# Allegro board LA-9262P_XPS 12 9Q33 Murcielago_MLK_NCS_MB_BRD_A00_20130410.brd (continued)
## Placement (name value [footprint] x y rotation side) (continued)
R537  -  [R_0402]  166.22 57.7 90 top
R540  -  [R_0402]  168.23 75.68 0 top
R541  -  [R_0805]  166.39 77.11 0 top
R545  -  [R_0402]  159.06 77.94 180 top
R555  -  [R_0402]  214.18 41.19 270 bottom
R556  -  [R_0402]  215.2 41.19 270 bottom
R560  -  [R_0402]  212.29 41.19 270 bottom
R565  -  [R_0402]  213.3 41.19 270 bottom
R604  -  [R_0402]  136.36 54.95 0 top
R607  -  [R_0402]  145.18 66.04 270 top
R608  -  [R_0402]  131.16 71.72 270 top
R741  -  [R0402_0OHM]  181.39 37.1 270 top
R742  -  [R0402_0OHM]  182.4 37.1 270 top
R811  -  [R_0603]  133.47 52.92 0 top
R819  -  [R0402_0OHM]  154.92 67.14 0 top
R854  -  [R_0402]  155.38 55.64 90 top
R855  -  [R_0402]  154.11 55.64 90 top
R884  -  [R_0402]  6.1 22.01 180 top
R886  -  [R_0402]  9.63 21.6 270 top
R888  -  [R_0402]  215.07 56.81 270 top
R889  -  [R_0402]  214.05 56.81 270 top
R890  -  [R_0402]  214.7 64.05 270 bottom
R891  -  [R_0402]  215.72 64.05 270 bottom
R892  -  [R_0402]  213.68 64.05 270 bottom
R893  -  [R_0402]  212.67 64.05 270 bottom
R910  -  [R_0402]  230.18 15.3 270 top
R911  -  [R_0402]  230.18 11.74 270 top
R912  -  [R_0402]  230.18 9.45 270 top
R913  -  [R_0402]  230.18 6.09 90 top
R916  -  [R_0402]  230.18 4.88 270 top
R920  -  [R_0402]  229.31 4.88 270 top
R921  -  [R0402_0OHM]  148.37 68.64 90 top
R922  -  [R_0402]  150.55 60.21 90 top
R924  -  [R_0402]  136.36 53.17 0 top
R925  -  [R0402_0OHM]  147.56 63.31 0 top
R926  -  [R0402_0OHM]  140.27 52.46 90 top
R927  -  [R_0402]  146.34 53.07 90 top
R928  -  [R_0402]  147.2 53.99 270 top
R929  -  [R_0402]  136.38 59.02 0 top
R930  -  [R_0402]  146.1 67.82 270 top
R931  -  [R0402_0OHM]  149.61 67.77 270 top
R934  -  [R0402_0OHM]  158.19 52.26 0 top
R939  -  [R_0402]  132.65 54.11 90 top
R941  -  [R_0402]  131.63 54.11 90 top
R942  -  [R_0402]  189.67 37.07 270 top
R943  -  [R_0402]  172.9 27.01 180 top
R944  -  [R_0402]  173.02 24.17 90 top
R945  -  [R_0402]  172.13 25.08 270 top
R953  -  [R_0402]  26.3 19.6 0 bottom
R955  -  [R_0402]  26.29 21.41 0 bottom
R957  -  [R_0402]  26.29 23.32 0 bottom
R973  -  [R_0402]  156.78 30.52 270 bottom
R974  -  [R0402_0OHM]  155.76 29.6 90 bottom
R975  -  [R_0402]  132.26 71.01 90 top
R977  -  [R_0402]  177.11 75.96 90 bottom
R978  -  [R_0402]  176.22 76.87 270 bottom
R980  -  [R_0402]  137.29 61.68 180 top
R982  -  [R0402_0OHM]  148.71 66.85 90 top
R983  -  [R0402_0OHM]  150.48 77.44 0 top
R984  -  [R0402_0OHM]  150.48 76.49 0 top
R985  -  [R_0402]  152.66 77.44 0 top
R986  -  [R_0402]  152.67 76.48 0 top
R989  -  [R_0402]  176.46 25.92 90 top
R990  -  [R_0402]  175.19 22.77 180 top
R1003  -  [R_0402]  152.39 66.26 0 top
R1004  -  [R_0402]  181.93 72.78 90 bottom
R1005  -  [R_0402]  180.92 72.78 90 bottom
R1006  -  [R0402_0OHM]  165.54 75.83 90 bottom
R1007  -  [R0402_0OHM]  164.52 75.83 90 bottom
R1008  -  [R0402_0OHM]  163.63 75.83 90 bottom
R1009  -  [R0402_0OHM]  162.62 75.83 90 bottom
R1010  -  [R0402_0OHM]  160.98 75.83 90 bottom
R1011  -  [R0402_0OHM]  159.96 75.83 90 bottom
R1026  -  [R_0402]  174.81 68.03 270 top
R1027  -  [R_0402]  133.29 21.62 180 bottom
R1032  -  [R_0402]  141.64 52.59 90 top
R1033  -  [R_0402]  159.15 74.05 270 bottom
R1034  -  [R_0402]  161.82 73.14 90 bottom
R1088  -  [R_0402]  153.18 55.54 90 top
R1090  -  [R_0402]  152.39 68.03 0 top
R1091  -  [R_0402]  145.13 73.36 180 top
R1092  -  [R_0402]  155.84 66.26 180 top
R1099  -  [R_0402]  154.93 62.45 0 top
R1100  -  [R_0402]  154.74 30.52 270 bottom
R1103  -  [R_0402]  6.1 21.12 180 top
R1115  -  [R_0402]  150.46 68.77 180 top
R1116  -  [R_0402]  150.57 67.63 0 top
R1117  -  [R_0402]  206 44.67 180 top
R1118  -  [R_0402]  206.86 44.67 0 top
R1125  -  [R0603_0OHM]  124.96 34.63 180 top
R1128  -  [R0603_0OHM]  178.11 34.76 270 top
R1131  -  [R0402_0OHM]  189.3 38.67 0 top
R1132  -  [R_0402]  23.66 53.47 180 top
R1133  -  [R0402_0OHM]  144.91 68.92 180 top
R1135  -  [R0402_0OHM]  159.58 67.96 90 top
R1136  -  [R_0402]  158.69 67.96 90 top
R1137  -  [R_0402]  196.91 41.31 180 top
R1139  -  [R_0402]  180.27 75.96 90 bottom
R1140  -  [R_0402]  130.41 31.71 0 top
R1141  -  [R_0402]  152.39 68.92 0 top
R1142  -  [R_0402]  157.79 29.6 90 bottom
R1143  -  [R_0402]  151.4 68.57 90 top
R1146  -  [R0402_0OHM]  132.38 22.59 0 bottom
R1152  -  [R0402_0OHM]  152.51 73.75 0 top
R1153  -  [R0402_0OHM]  152.51 74.64 0 top
R1154  -  [R_0402]  144 69.81 0 top
R1156  -  [R_0402]  129.52 58.64 0 top
R1158  -  [R0402_0OHM]  163.56 64.86 0 top
R1160  -  [R_0402]  125.29 60.36 90 top
R1161  -  [R_0402]  158.43 85.76 270 top
R1162  -  [R_0402]  174.81 69.89 270 top
R1163  -  [R_0402]  176.45 41.11 90 top
R1164  -  [R_0402]  202.03 40.08 270 top
R1165  -  [R_0402]  207.7 38.52 270 top
R1166  -  [R0402_0OHM]  205.42 38.52 270 top
R1167  -  [R_0402]  203.5 40.07 270 top
R1169  -  [R_0402]  111.63 72.48 270 bottom
R1175  -  [R_0402]  154.48 82.61 270 top
R1176  -  [R_0402]  145.99 73.36 0 top
R1179  -  [R_0402]  52.72 79.72 0 top
R1180  -  [R_0402]  22.75 52.58 0 top
R1182  -  [R_0402]  130.41 30.7 0 top
R1183  -  [R_0402]  127.18 60.49 270 top
R1185  -  [R_0402]  111.6 73.39 0 bottom
R1186  -  [R_0402]  131.69 43.98 270 top
R1187  -  [R_0402]  132.65 42.13 0 top
R1188  -  [R0402_0OHM]  194.84 53.48 270 top
R1190  -  [R_0402]  117.08 64.86 0 top
R1191  -  [R_0402]  117.08 66.64 0 top
R1197  -  [R_0402]  196.91 40.39 180 top
R1198  -  [R_0402]  35.67 45.81 0 top
R1199  -  [R0402_0OHM]  190.22 40.88 180 top
R1200  -  [R_0402]  190.65 43.69 90 top
R1202  -  [R_0402]  168.85 63.14 180 top
R1203  -  [R_0402]  173.68 67.32 90 top
R1204  -  [R0402_0OHM]  186.71 54.85 90 top
R1205  -  [R0402_0OHM]  140.76 76.96 180 top
R1206  -  [R_0402]  139.85 76.07 0 top
R1207  -  [R_0402]  165.41 66.48 180 top
R1208  -  [R0402_0OHM]  196.18 45.02 270 top
R1209  -  [R_0402]  197.09 45.02 270 top
R1210  -  [R_0402]  193.53 41.27 270 top
R1211  -  [R_0402]  58.13 84.21 90 top
R1212  -  [R_0402]  194.44 41.27 270 top
R1213  -  [R_0402]  206.31 38.52 270 top
R1214  -  [R_0402]  173.17 59.78 180 top
R1215  -  [R_0402]  173.17 58.85 180 top
R1216  -  [R0402_0OHM]  175.94 61.48 180 top
R1217  -  [R_0402]  216.14 46.08 180 top
R1218  -  [R_0402]  152.51 73.75 0 bottom
R1219  -  [R_0402]  152.51 74.64 0 bottom
R1220  -  [R_0402]  160.2 59.22 270 top
R1221  -  [R0402_0OHM]  158.43 58.56 90 top
R1222  -  [R0402_0OHM]  157.54 58.56 90 top
R1223  -  [R_0402]  155.76 59.73 270 top
R1224  -  [R_0402]  164.47 62.06 180 top
R1225  -  [R_0402]  164.47 62.95 180 top
R1226  -  [R0603_0OHM]  178.57 40.35 0 top
R1227  -  [R_0402]  165.08 58.57 270 top
R1228  -  [R_0402]  153.73 29.6 90 bottom
R1238  -  [R0402_0OHM]  135.41 76.26 0 top
R1239  -  [R_0402]  135.41 77.15 0 top
R1240  -  [R_1206]  94.15 74.51 180 top
R1241  -  [R_0402]  56.35 84.21 90 top
R1242  -  [R0603_0OHM]  160.71 31.03 270 bottom
R1247  -  [R0402_0OHM]  167.19 44.08 90 top
R1249  -  [R_0402]  127.18 61.48 90 top
R1250  -  [R_0402]  169.35 46.06 0 top
R1251  -  [R_0402]  154.88 58.81 90 top
R1252  -  [R0402_0OHM]  162.01 58.31 90 top
R1253  -  [R_0402]  162.87 59.22 270 top
R1255  -  [R_0402]  193.69 43.68 90 top
R1257  -  [R0402_0OHM]  136.52 27.27 0 top
R1258  -  [R0402_0OHM]  136.52 26.38 0 top
R1261  -  [R_0402]  118.66 39.13 0 top
R1262  -  [R_0402]  118.66 40.02 0 top
R1263  -  [R_0402]  125.48 52.49 270 top
R1264  -  [R_0402]  118.66 37.35 0 top
R1265  -  [R_0402]  124.47 52.49 270 top
R1266  -  [R_0402]  118.66 38.24 0 top
R1279  -  [R_0402]  181.16 75.96 90 bottom
R1281  -  [R_0402]  173.79 54.57 0 top
R1282  -  [R_0402]  173.04 51.09 270 top
R1283  -  [R_0402]  172.92 44.97 90 top
R1284  -  [R_0402]  175.08 45.89 270 top
R1285  -  [R_0402]  172.16 51.09 270 top
R1286  -  [R_0402]  171.27 51.09 270 top
R1287  -  [R_0402]  170.38 50.18 90 top
R1289  -  [R_0402]  163.21 54.19 180 top
R1290  -  [R_0402]  159.15 49.62 180 top
R1291  -  [R_0402]  160.4 54.19 0 top
R1292  -  [R_0402]  162.96 47.97 180 top
R1293  -  [R0402_0OHM]  157.28 49.57 270 top
R1294  -  [R0402_0OHM]  159.15 48.65 180 top
R1295  -  [R_0402]  159.15 50.51 180 top
R1296  -  [R_0402]  159.15 51.4 180 top
R1297  -  [R_0402]  147.49 69.56 270 top
R1299  -  [R_0402]  132.98 28.59 90 bottom
R1305  -  [R0603_0OHM]  132.77 22.95 270 top
R1306  -  [R_0603]  131.38 22.95 270 top
R1307  -  [R_0402]  150.93 71.64 90 top
R1308  -  [R_0402]  147.67 72.28 270 top
R1309  -  [R_0402]  22.75 44.96 0 top
R1310  -  [R_0402]  133.07 63.25 180 top
R1311  -  [R_0402]  21.86 47.08 180 bottom
R1312  -  [R_0402]  22.41 50.43 90 top
R1313  -  [R_0402]  187.33 42.6 270 top
R1314  -  [R0402_0OHM]  188.22 42.6 270 top
R1318  -  [R0603_0OHM]  125.05 30.82 180 top
R1319  -  [R0603_0OHM]  168.33 50.25 90 top
R1320  -  [R0603_0OHM]  121.28 60.03 180 top
R1322  -  [R0805_0OHM]  171.11 77.91 270 bottom
R1324  -  [R_0402]  35.16 54.53 0 bottom
R1325  -  [R_0402]  37.83 54.53 180 bottom
R1326  -  [R0603_0OHM]  121.3 56.73 180 top
R1327  -  [R_0402]  188.16 36.21 90 top
R1328  -  [R_0402]  187.27 36.21 90 top
R1338  -  [R_0402]  168.85 64.03 180 top
R1341  -  [R_0402]  94.7 48.33 90 top
R1342  -  [R_0402]  183.78 73.11 180 bottom
R1346  -  [R_0402]  114.71 50.89 0 top
R1347  -  [R_0402]  114.71 51.79 0 top
R1348  -  [R_0402]  113.02 54.97 90 top
R1349  -  [R_0402]  112.06 54.97 90 top
R1350  -  [R_0402]  114.71 52.69 0 top
R1351  -  [R_0402]  114.71 50 0 top
R1353  -  [R0402_0OHM]  144.22 72.45 0 top
R1354  -  [R_0402]  137.29 57.67 180 top
R1355  -  [R_1206]  110.08 60.93 90 top
R1360  -  [R_0402]  184.04 41.16 270 top
R1361  -  [R_0402]  183.34 36.21 90 top
R1362  -  [R_0402]  184.22 36.21 90 top
R1363  -  [R_0402]  185.12 36.21 90 top
R1364  -  [R_0402]  186.01 36.21 90 top
R1365  -  [R_0402]  186.38 41.95 270 top
R1366  -  [R_0402]  162.92 46.95 0 top
R1367  -  [R_0402]  161.09 59.22 270 top
R1368  -  [R_0402]  188.23 44.59 270 top
R1369  -  [R_0402]  189.49 44.6 270 top
R1370  -  [R_0402]  191.66 44.59 270 top
R1371  -  [R_0402]  192.68 44.59 270 top
R1372  -  [R0402_0OHM]  125.15 38.11 90 top
R1373  -  [R_0402]  131.76 41.24 180 top
R1374  -  [R_0402]  131.76 42.13 180 top
R1375  -  [R_0402]  125.25 50.48 270 top
R1376  -  [R_0402]  153.42 75.68 180 bottom
R1377  -  [R_0402]  138.41 30.95 270 top
R1378  -  [R_0402]  139.33 30.95 270 top
R1379  -  [R_0402]  118.52 78.63 0 top
R1380  -  [R_0402]  118.52 77.51 0 top
R1381  -  [R_0402]  117.52 73.88 180 top
R1382  -  [R0402_0OHM]  126.18 61.28 270 top
R1384  -  [R_0402]  169.48 75.2 270 bottom
R1385  -  [R_0402]  167.63 74.31 0 bottom
R1386  -  [R_0402]  131.57 57.57 90 top
R1387  -  [R_0402]  138.03 30.43 180 bottom
R1388  -  [R_0402]  173.44 39.07 270 top
R1389  -  [R_0402]  153.23 76.62 0 bottom
R1390  -  [R0402_0OHM]  119.13 64.45 0 bottom
R1391  -  [R_0402]  120.05 63.56 180 bottom
R1392  -  [R0603_0OHM]  158.45 75.22 0 top
R1393  -  [R0603_0OHM]  157.89 72.31 180 top
R1394  -  [R_0402]  153.42 75.55 180 top
R1395  -  [R_0402]  182.82 39.64 90 top
RA1  -  [R_0402]  124.33 50.46 270 top
RA5  -  [R_0402]  131.71 47.33 180 top
RA6  -  [R_0402]  131.71 48.22 180 top
RA7  -  [R_0402]  124.26 39.03 270 top
RA8  -  [R_0402]  123.37 39.03 270 top
RA9  -  [R0402_0OHM]  132.57 47.33 0 top
RA10  -  [R0402_0OHM]  132.57 48.22 0 top
RA11  -  [R0402_0OHM]  117.28 44.59 90 top
RA12  -  [R0402_0OHM]  114.99 47.9 0 top
RA13  -  [R0402_0OHM]  121.17 51.24 180 top
RA14  -  [R0402_0OHM]  118.14 42.34 180 top
RA15  -  [R0402_0OHM]  117.8 40.02 180 top
RA16  -  [R_0402]  117.23 41.39 0 top
RA17  -  [R_0402]  119.01 41.4 0 top
RA18  -  [R_0402]  109.18 46.06 0 top
RA19  -  [R_0402]  109.18 47.05 0 top
RA20  -  [R_0402]  109.19 47.97 0 top
RC36  -  [R_0402]  85.64 77.83 270 top
RC41  -  [R_0402]  52.67 76.61 0 bottom
RC43  -  [R_0402]  31.59 83.31 90 bottom
RC44  -  [R_0402]  53.43 85.13 270 bottom
RC45  -  [R_0402]  53.62 79.64 180 bottom
RC46  -  [R_0402]  53.65 78.77 180 bottom
RC48  -  [R_0402]  53.65 77.88 180 bottom
RC49  -  [R0402_0OHM]  55.21 84.21 90 bottom
RC52  -  [R_0402]  60.29 84.14 90 bottom
RC54  -  [R_0402]  61.18 84.14 90 bottom
RC55  -  [R_0402]  60.15 55.47 270 top
RC58  -  [R_0402]  59.01 55.47 270 top
RC60  -  [R_0402]  57.86 55.47 270 top
RC75  -  [R_0402]  86.18 50.11 90 bottom
RC81  -  [R_0402]  53.65 68.54 180 bottom
RC92  -  [R0402_0OHM]  52.67 72.16 0 bottom
RC93  -  [R_0402]  53.58 73.94 180 bottom
RC94  -  [R_0402]  52.67 73.05 0 bottom
RC95  -  [R_0402]  52.66 75.37 0 bottom
RC96  -  [R0402_0OHM]  50.2 75.12 0 bottom
RC97  -  [R_0402]  52.71 83.19 0 bottom
RC98  -  [R0402_0OHM]  52.71 82.3 0 bottom
RC99  -  [R0402_0OHM]  53.62 81.42 180 bottom
RC100  -  [R_0402]  53.62 80.53 180 bottom
RC138  -  [R_0402]  110.6 77.84 270 top
RC146  -  [R_0402]  68.96 83.19 90 bottom
RC147  -  [R0402_0OHM]  97.31 84.09 270 bottom
RC148  -  [R0402_0OHM]  113.51 79.82 90 top
RC149  -  [R_0402]  54.32 85.13 270 bottom
RC150  -  [R0402_0OHM]  56.46 85.13 270 bottom
RC151  -  [R0402_0OHM]  56.35 82.84 270 top
RC152  -  [R0402_0OHM]  57.24 85.13 270 top
RC153  -  [R_0402]  53.65 69.56 180 bottom
RC154  -  [R_0402]  88.58 55.21 270 top
RC155  -  [R_0402]  93.92 83.32 90 bottom
RC156  -  [R_0402]  87.05 57.37 180 top
RC158  -  [R_0402]  68.07 84.1 270 bottom
RC159  -  [R_0402]  48.1 58.89 0 bottom
RC160  -  [R_0402]  109.63 77.84 270 top
RC161  -  [R_0402]  49.01 58 180 bottom
RC162  -  [R0402_0OHM]  86.18 52.87 270 bottom
RD1  -  [R_0402]  18.42 34.51 180 top
RD2  -  [R_0402]  27.87 35.95 90 top
RD3  -  [R_0402]  44.44 47.71 180 bottom
RD4  -  [R_0402]  45.44 47.71 0 bottom
RD5  -  [R_0402]  46.84 32.47 0 top
RD6  -  [R_0402]  52.64 34.58 270 top
RD7  -  [R_0402]  64.9 32.47 180 top
RD8  -  [R_0402]  75.62 34.58 270 top
RD9  -  [R_0402]  53.82 47.69 180 bottom
RD10  -  [R_0402]  56.89 47.71 180 bottom
RD11  -  [R_0402]  94.47 32.47 0 top
RD12  -  [R_0402]  100.51 35.45 90 top
RD13  -  [R_0402]  57.51 51.02 0 top
RD14  -  [R_0402]  60.21 52.79 180 top
RD15  -  [R_0402]  58.43 52.79 180 top
RD16  -  [R_0402]  59.29 51.02 0 top
RD17  -  [R_0402]  65.59 51.45 90 top
RD18  -  [R_0402]  61.07 51.02 0 top
RD19  -  [R_0402]  65.72 54.27 270 top
RD20  -  [R_0402]  62.8 52.87 270 top
RD21  -  [R_0402]  64.7 52.36 270 top
RD22  -  [R_0402]  61.91 51.96 90 top
RD23  -  [R_0402]  66.48 52.36 270 top
RD24  -  [R_0402]  63.76 51.02 180 top
RD25  -  [R_0402]  39.48 30.54 180 top
RD26  -  [R_0402]  85.58 32.6 0 top
RD27  -  [R_0402]  37.95 32.85 0 top
RD28  -  [R_0402]  88.28 32.6 180 top
RD29  -  [R_0402]  41.71 28.84 0 top
RD30  -  [R_0402]  83.95 29.04 180 top
RD31  -  [R_0402]  42.48 36.46 90 top
RD32  -  [R_0402]  89.21 34.68 90 top
RD33  -  [R_0402]  39.76 29.3 180 top
RD34  -  [R_0402]  84.77 26.05 90 top
RD35  -  [R_0402]  36 27.7 90 top
RD36  -  [R_0402]  87.54 28.89 90 top
RD37  -  [R_0402]  41.68 29.78 0 top
RD38  -  [R_0402]  89.42 30.31 180 top
RD39  -  [R_0402]  40.15 27.27 0 top
RD40  -  [R_0402]  83.83 26.38 180 top
RD41  -  [R_0402]  43.8 28.79 0 top
RD42  -  [R_0402]  88.63 26.25 0 top
RD43  -  [R_0402]  41.97 25.62 90 top
RD44  -  [R_0402]  90.61 27.85 270 top
RD45  -  [R_0402]  36.89 27.83 90 top
RD46  -  [R_0402]  92.51 25.92 90 top
RD47  -  [R_0402]  36.05 26.12 0 top
RD48  -  [R_0402]  91.62 25.92 90 top
RD49  -  [R_0402]  39.43 25.51 90 top
RD50  -  [R_0402]  84.77 28.97 0 top
RD51  -  [R_0402]  43.75 25.62 90 top
RD52  -  [R_0402]  86.54 27.06 90 top
RD53  -  [R_0402]  42.86 25.62 90 top
RD54  -  [R_0402]  88.63 27.14 0 top
RD55  -  [R_0402]  38.04 25.59 90 top
RD56  -  [R_0402]  85.66 27.06 90 top
RD57  -  [R_0402]  41.59 36.46 90 top
RD58  -  [R_0402]  86.16 34.71 270 top
RD59  -  [R_0402]  41.16 34.12 180 top
RD60  -  [R_0402]  89.43 31.2 180 top
RD61  -  [R_0402]  43.42 31.33 0 top
RD62  -  [R_0402]  88.27 33.49 180 top
RD63  -  [R_0402]  41.16 33.24 180 top
RD64  -  [R_0402]  88.27 34.38 180 top
RD65  -  [R_0402]  41.16 35.01 180 top
RD66  -  [R_0402]  91.04 30.44 0 top
RD67  -  [R_0402]  39.81 31.38 90 top
RD68  -  [R_0402]  86.67 30.62 90 top
RD69  -  [R_0402]  36.89 30.52 270 top
RD70  -  [R_0402]  91.07 29.58 270 top
RD71  -  [R_0402]  40.72 31.36 90 top
RD72  -  [R_0402]  90.23 34.68 90 top
RD73  -  [R_0402]  26.93 33.74 180 top
RD74  -  [R_0402]  110.6 34.51 0 top
RD75  -  [R_0402]  40.52 39.33 180 top
RD76  -  [R_0402]  88.41 38.57 180 top
RD77  -  [R_0402]  40.52 38.44 180 top
RD78  -  [R_0402]  88.41 37.68 180 top
RD79  -  [R_0402]  18.42 33.62 180 top
RD80  -  [R_0402]  26.98 35.95 90 top
RD81  -  [R_0402]  46.84 33.36 0 top
RD82  -  [R_0402]  53.52 34.58 270 top
RD83  -  [R_0402]  64.9 33.36 180 top
RD84  -  [R_0402]  76.51 34.58 270 top
RD85  -  [R_0402]  94.47 33.36 0 top
RD86  -  [R_0402]  101.66 35.19 90 top
RD87  -  [R_0402]  40.7 36.46 90 top
RD88  -  [R_0402]  43.42 30.44 0 top
RD89  -  [R_0402]  87.1 36.54 0 top
RD90  -  [R_0402]  91.04 31.33 0 top
RH2  -  [R_0402]  103.02 51.78 180 bottom
RH11  -  [R_0402]  97 51.96 90 bottom
RH12  -  [R_0402]  97.14 64.4 270 top
RH21  -  [R_0402]  24.19 50.43 90 top
RH23  -  [R_0402]  94.83 53.01 90 top
RH24  -  [R_0402]  90.24 49.16 90 bottom
RH25  -  [R_0402]  93.94 53.01 90 top
RH29  -  [R_0402]  109.75 71.46 180 bottom
RH31  -  [R_0402]  93.9 51.93 90 bottom
RH32  -  [R_0402]  90.6 72.11 0 top
RH34  -  [R_0402]  93.88 49.8 90 bottom
RH35  -  [R_0402]  104.53 69.99 0 bottom
RH37  -  [R_0402]  103.54 71.76 180 bottom
RH38  -  [R_0402]  52.73 67.65 0 bottom
RH39  -  [R_0402]  52.73 65.62 0 bottom
RH40  -  [R_0402]  52.73 66.64 0 bottom
RH42  -  [R_0402]  89.64 53.89 270 bottom
RH43  -  [R_0402]  94.81 84.24 270 bottom
RH51  -  [R_0402]  22.75 49.4 0 top
RH53  -  [R_0402]  52.73 62.45 0 bottom
RH54  -  [R_0402]  115.49 56.29 270 bottom
RH56  -  [R_0402]  115.13 59.98 270 bottom
RH70  -  [R_0402]  99.44 58.86 90 top
RH72  -  [R_0402]  100.44 58.86 90 top
RH76  -  [R_0402]  70.81 83.2 90 bottom
RH77  -  [R_0402]  71.7 83.2 90 bottom
RH78  -  [R_0402]  92.77 62.78 270 top
RH79  -  [R_0402]  91.62 62.78 270 top
RH91  -  [R_0402]  104.53 70.87 0 bottom
RH95  -  [R_0402]  107.84 69.74 180 bottom
RH98  -  [R_0402]  123.45 61.43 180 top
RH99  -  [R_0402]  123.45 60.54 180 top
RH100  -  [R_0402]  103.77 69.11 180 bottom
RH103  -  [R_0402]  108.82 75.26 0 bottom
RH105  -  [R_0402]  120.12 61.3 0 top
RH107  -  [R_0402]  107.84 73.25 180 bottom
RH110  -  [R_0402]  103.54 72.64 180 bottom
RH111  -  [R_0402]  122.82 64.73 180 top
RH113  -  [R_0402]  81.45 82.4 90 top
RH117  -  [R_0402]  85 81.62 180 top
RH123  -  [R_0402]  96.43 84.09 270 bottom
RH126  -  [R_0402]  98.91 53.76 180 top
RH128  -  [R0402_0OHM]  116.97 66.42 180 bottom
RH131  -  [R0402_0OHM]  96.22 64.4 270 top
RH132  -  [R0402_0OHM]  94.2 66.71 270 top
RH133  -  [R0402_0OHM]  98.01 52.87 270 top
RH137  -  [R0402_0OHM]  97.39 65.75 0 top
RH146  -  [R_0402]  107.32 63.67 90 top
RH147  -  [R_0402]  94.92 51.93 90 bottom
RH151  -  [R_0402]  94.9 49.8 90 bottom
RH154  -  [R_0402]  114.79 52.13 270 bottom
RH158  -  [R_0402]  99.35 84.09 270 bottom
RH159  -  [R_0402]  98.01 50.08 90 top
RH163  -  [R_0402]  89.8 62.19 180 top
RH168  -  [R_0402]  119.06 53.48 90 bottom
RH171  -  [R_0402]  118.17 53.48 90 bottom
RH180  -  [R_0402]  112.54 71.56 90 bottom
RH183  -  [R_0402]  120 53.48 90 bottom
RH186  -  [R_0402]  118.76 68.29 180 bottom
RH188  -  [R_0402]  105.81 66.26 180 bottom
RH196  -  [R_0402]  109.16 69.61 90 bottom
RH248  -  [R_0402]  107.84 70.61 180 bottom
RH255  -  [R_0402]  96.88 69.79 180 top
RH270  -  [R_0402]  93.32 67.7 90 top
RH271  -  [R_0402]  111.72 67.25 0 bottom
RH272  -  [R_0402]  96.1 66.71 270 top
RH274  -  [R_0402]  116.07 70.7 0 bottom
RH281  -  [R_0402]  194.16 76.64 0 top
RH282  -  [R_0402]  194.18 73.96 0 top
RH293  -  [R0402_0OHM]  93.61 62.83 0 top
RH294  -  [R_0402]  117.89 64.26 180 bottom
RH295  -  [R_0402]  96.7 57.3 270 top
RH297  -  [R0402_0OHM]  113.9 52.13 270 bottom
RH300  -  [R_0402]  98.33 84.09 270 bottom
RH302  -  [R_0402]  102.62 70.87 0 bottom
RH303  -  [R_0402]  114.56 69.68 180 bottom
RH309  -  [R0402_0OHM]  98.9 51.96 90 top
RH310  -  [R_0402]  116.97 67.4 180 bottom
RH313  -  [R0402_0OHM]  97.89 51.96 90 bottom
RH314  -  [R_0402]  112.63 66.36 180 bottom
RH315  -  [R_0402]  112.52 70.42 180 bottom
RH316  -  [R_0402]  113.65 70.7 0 bottom
RH337  -  [R_0402]  117.98 70.7 0 bottom
RH338  -  [R_0402]  80.56 83.31 270 top
RH340  -  [R0805_0OHM]  87.82 66.64 180 top
RH341  -  [R0402_0OHM]  88.96 63.97 90 top
RH346  -  [R0402_0OHM]  84.46 65.11 180 top
RH348  -  [R0402_0OHM]  104.97 63.77 90 top
RH350  -  [R0603_0OHM]  98.19 72.52 270 top
RH351  -  [R_0603]  103.69 63.27 90 top
RH354  -  [R_0603]  99.45 73.62 0 top
RH355  -  [R0402_0OHM]  91.57 81.5 180 top
RH356  -  [R0402_0OHM]  92.95 80.57 90 top
RH360  -  [R_0402]  90.82 60.29 0 top
RH363  -  [R_0402]  35.74 52.3 0 top
RH364  -  [R_0402]  102.62 74.48 0 bottom
RH365  -  [R_0402]  102.62 73.52 0 bottom
RH367  -  [R_0402]  35.74 49.63 0 top
RH369  -  [R_0402]  36.64 46.93 180 top
RH370  -  [R_0402]  42.06 51.78 180 bottom
RH371  -  [R_0402]  33.8 46.32 180 bottom
RH372  -  [R_0402]  32.96 48.58 0 bottom
RH373  -  [R_0402]  22.75 47.62 0 top
RH374  -  [R_0402]  22.75 45.85 0 top
RH375  -  [R_0402]  52.73 64.6 0 bottom
RH380  -  [R_0402]  107.84 74.13 180 bottom
RH381  -  [R_0402]  186.42 44.55 270 top
RH383  -  [R_0402]  117.89 63.25 180 bottom
RH384  -  [R_0402]  109.74 73.49 180 bottom
RH386  -  [R_0402]  90.82 58.25 0 top
RH390  -  [R_0402]  106.93 72.36 0 bottom
RH391  -  [R_0402]  106.93 71.49 0 bottom
RH392  -  [R_0402]  102.62 70 0 bottom
RH394  -  [R_0402]  95.86 52.87 270 bottom
RH395  -  [R_0402]  98.47 56.39 90 top
RH396  -  [R_0402]  108.82 74.38 0 bottom
RH397  -  [R_0402]  113.65 72.73 0 bottom
RH398  -  [R_0402]  97.58 56.39 90 top
RH400  -  [R_0402]  99.77 61.38 270 bottom
RH401  -  [R_0402]  101.85 52.79 0 top
RH402  -  [R_0402]  106.1 63.77 90 top
RH405  -  [R_0603]  106.48 71.49 180 top
RH406  -  [R_0603]  105.1 70.24 0 top
RH410  -  [R_0402]  195.9 35.47 0 top
RH411  -  [R_0402]  22.75 46.74 0 top
RH412  -  [R_0402]  21.7 44.03 0 top
RH413  -  [R_0402]  36.64 47.82 180 top
RH414  -  [R_0402]  32.89 47.21 0 bottom
RH415  -  [R_0402]  114.56 68.67 180 bottom
RH416  -  [R_0402]  111.72 68.14 0 bottom
RH423  -  [R_0402]  128.06 65.67 90 top
RH424  -  [R_0402]  99.82 77.18 0 bottom
RH425  -  [R_0402]  99.82 78.07 0 bottom
RH426  -  [R_0402]  91.84 55.42 0 top
RH427  -  [R0402_0OHM]  116.99 68.29 180 bottom
RH428  -  [R_0402]  90.82 59.27 0 top
RH429  -  [R_0402]  115.68 51.22 90 bottom
RH430  -  [R0402_0OHM]  116.59 52.13 270 bottom
RH431  -  [R_0402]  128.95 66.59 270 top
RH434  -  [R_0402]  96.83 73.41 90 top
RH435  -  [R_0402]  95.75 74.32 270 top
RH438  -  [R_0402]  96.97 66.87 0 top
RH439  -  [R_0402]  132.49 58.46 0 top
RH440  -  [R_0402]  116.99 71.72 180 bottom
RH441  -  [R_0402]  116.99 72.73 180 bottom
RH442  -  [SHORTPADS]  118.56 71.84 0 bottom
RH443  -  [SHORTPADS]  118.05 73.62 90 bottom
RH444  -  [R_0402]  23.3 50.43 90 top
RH445  -  [R_0402]  52.73 63.59 0 bottom
RH446  -  [R_0402]  21.97 46.06 0 bottom
RH450  -  [R0402_0OHM]  102.86 68.22 0 bottom
RH451  -  [R_0402]  35.74 51.41 0 top
RH452  -  [R_0402]  88.34 71.29 90 top
RH453  -  [R_0402]  124.31 61.44 270 top
RH454  -  [R_0402]  125.81 64.76 180 top
RH457  -  [R_0402]  99.74 74.54 0 bottom
RH458  -  [R_0402]  99.74 75.43 0 bottom
RH459  -  [R_0402]  191.41 54.72 90 top
RH460  -  [R_0402]  192.3 54.72 90 top
RH461  -  [R_0402]  165.46 62.95 0 top
RH462  -  [R_0402]  165.46 62.06 0 top
RH463  -  [R_0402]  119.13 62.67 0 bottom
RH465  -  [R_0402]  90.01 74.46 180 top
RP2  -  [RP_0804_8P4R]  101.36 73.36 180 bottom
RP3  -  [RP_0804_8P4R]  92.39 52.35 90 bottom
RP4  -  [RP_0804_8P4R]  100.42 67.89 180 top
RP7  -  [RP_0804_8P4R]  103.89 63.6 0 bottom
RP11  -  [RP_0804_8P4R]  99.18 62.43 0 top
RP12  -  [RP_0804_8P4R]  154.3 65.1 0 top
RP14  -  [RP_0804_8P4R]  226.95 23.85 180 top
RP15  -  [RP_0804_8P4R]  149.21 56.92 180 top
RP16  -  [RP_0804_8P4R]  148.06 61.24 0 top
RP19  -  [RP_0804_8P4R]  100.33 63.47 0 bottom
RP20  -  [RP_0804_8P4R]  99.56 65.35 0 top
RP21  -  [RP_0804_8P4R]  136.9 63.22 180 top
RP22  -  [RP_0804_8P4R]  139.95 49.89 180 top
RTCD1  -  [BAT54CW-7-F_SOT323-3]  32.77 52.86 0 bottom
RTCR1  -  [R_0402]  31.12 55.58 180 bottom
RV1  -  [R_1206]  213.27 71.42 90 bottom
RV2  -  [R_0402]  195.1 73.04 180 top
RV3  -  [R_0402]  195.08 75.7 180 top
RV4  -  [R_0402]  217.51 72.14 90 bottom
RV8  -  [R0402_0OHM]  201.82 73.46 0 bottom
RV9  -  [R_0402]  217.51 74.79 270 bottom
RV10  -  [R_0402]  215.46 64.41 0 top
SW1  -  [SW_EVQP3S01K_4P]  230.38 25.28 270 top
SW2  -  [SW_SKQGCBE010_4P]  105.79 23.53 180 bottom
T2  -  [TPC12]  49.3 78.69 180 bottom
T123  -  [TPC12]  99.73 66.1 180 bottom
T226  -  [TPC12]  50.98 84.15 180 bottom
T227  -  [TPC12]  54.76 76.11 180 bottom
T228  -  [TPC12]  50.74 82.23 180 bottom
T229  -  [TPC12]  54.5 77.38 180 bottom
T230  -  [TPC12]  50.93 78.26 180 bottom
T231  -  [TPC12]  49.52 80.91 180 bottom
T242  -  [TPC12]  166.58 53.78 0 top
T243  -  [TPC12]  166.28 52.36 0 top
T244  -  [TPC12]  177.92 49.42 180 bottom
T245  -  [TPC12]  177.9 47.41 180 bottom
T246  -  [TPC12]  178.49 45.81 180 bottom
T252  -  [TPC12]  165.2 67.63 0 top
T260  -  [TPC12]  159.32 60.01 0 top
T261  -  [TPC12]  161.09 55.63 0 top
T262  -  [TPC12]  173.04 44.06 0 top
T263  -  [TPC12]  56.08 76.09 180 bottom
T264  -  [TPC12]  55.49 74.82 180 bottom
T265  -  [TPC12]  59.54 83.15 0 top
T266  -  [TPC12]  50.92 78.31 0 top
T267  -  [TPC12]  62.49 83.15 0 top
T268  -  [TPC12]  54.99 79.88 0 top
T269  -  [TPC12]  54.77 77.44 0 top
T270  -  [TPC12]  99.09 69.41 180 bottom
T271  -  [TPC12]  100.06 70.65 180 bottom
T272  -  [TPC12]  105.61 68.92 180 bottom
T273  -  [TPC12]  54.56 65.17 180 bottom
T274  -  [TPC12]  101.78 68.83 180 bottom
T275  -  [TPC12]  54.6 63.82 180 bottom
T276  -  [TPC12]  54.61 65.8 180 bottom
T277  -  [TPC12]  54.66 62.03 180 bottom
T278  -  [TPC12]  54.63 66.43 180 bottom
T279  -  [TPC12]  97.86 70.03 0 top
T280  -  [TPC12]  94.34 68.44 0 top
T281  -  [TPC12]  98.65 71.2 180 bottom
T282  -  [TPC12]  147.76 29.18 0 top
T283  -  [TPC12]  97.76 59.11 0 top
T284  -  [TPC12]  101.8 54.7 180 bottom
T285  -  [TPC12]  119.95 58.99 180 bottom
T286  -  [TPC12]  115.51 69.68 180 bottom
T287  -  [TPC12]  110.65 69.66 180 bottom
T288  -  [TPC12]  120.12 60.53 180 bottom
T289  -  [TPC12]  98.11 64.76 0 top
T290  -  [TPC12]  98.78 60.92 180 bottom
T291  -  [TPC12]  98.51 63.36 0 top
T292  -  [TPC12]  104.38 53.54 180 bottom
T293  -  [TPC12]  55.84 67.59 180 bottom
U34  -  [KB9012BF-A3_LFBGA_128P]  145.42 62.1 270 top
U48  -  [W25Q64FVSSIQ_SO8]  113.55 54.24 180 bottom
U635  -  [SN74LVC1G06DCKR_SC70-5]  132.22 68.35 90 top
U636  -  [STM32F103RDY6TR_WLCSP_64P]  158.05 62.32 90 top
U637  -  [LSM303DLHCTR_LGA14_3X5]  155.49 53.33 180 top
U638  -  [L3GD20TR_LGA16_4X4]  143.08 78.84 270 top
U652  -  [AT97SC3204-X2A18-AB_TSSOP28]  134.83 74.67 270 top
U653  -  [LPS331APTR_HCLGA16_3X3]  150.54 79.48 0 top
U663  -  [74CBTLV3126DS_SSOP16]  40.97 50.44 270 bottom
U664  -  [TPS22966DPUR_SON14_2X3]  128.72 31.4 90 top
U671  -  [TXB0104PWR_TSSOP14]  189.71 47.21 0 top
U672  -  [74AUP1G07GW_TSSOP5]  23.71 57.03 180 top
U673  -  [NCP4545IMNTWG_QFN18_3X3]  114.73 68.29 180 top
U675  -  [SN74AHC1G08DCKR_SC70-5]  170.36 68.05 270 top
U676  -  [SN74CBT1G125DCKR_SC70-5]  170.49 62.97 270 top
U677  -  [TXB0104PWR_TSSOP14]  182.98 47.34 0 top
U679  -  [TXS0102YZPR_DSBGA_8P]  187.73 40.56 0 top
U682  -  [SN74AHC1G04DCKR_SOT23-5]  131.88 65.87 90 top
U687  -  [SN74AHC1G04DCKR_SOT23-5]  177.69 50.11 90 top
U688  -  [NC7SZ175P6X_SC70-6]  172.16 47.1 0 top
U689  -  [SN74AHC1G32DCKR_SC70-5]  176.01 48.89 180 top
U690  -  [SN74AHC1G08DCKR_SC70-5]  160.72 53.06 270 top
U691  -  [SN74AHC1G08DCKR_SC70-5]  160.72 50.4 270 top
U697  -  [SN74AHC1G08DCKR_SC70-5]  37.54 53.06 270 bottom
U698  -  [SN74AHC1G08DCKR_SC70-5]  131.91 59.75 0 top
U699  -  [SN74AHC1G32DCKR_SC70-5]  204.68 40.02 0 bottom
U708  -  [SN74AHC1G04DCKR_SOT23-5]  167.95 82.64 270 top
U709  -  [SN74AHC1G04DCKR_SOT23-5]  172.22 64.21 90 top
U710  -  [SN74AHC1G04DCKR_SOT23-5]  130.56 63.35 90 top
U712  -  [SN74AHC1G04DCKR_SOT23-5]  130.44 56.93 180 top
U713  -  [SN74AHC1G04DCKR_SOT23-5]  123.1 55.26 270 top
U714  -  [1337GNLGI8_QFN16_3X3]  111.03 50.58 0 top
U716  -  [TPS22966DPUR_SON14_2X3]  165.88 46.42 0 top
U717  -  [TPS22966DPUR_SON14_2X3]  136.61 23.64 270 top
U718  -  [TPS22966DPUR_SON14_2X3]  176.59 38.32 270 top
U719  -  [TPS22966DPUR_SON14_2X3]  124.91 56.42 90 top
U721  -  [APL3512ABI-TRG_SOT23-5]  173.12 77.51 0 bottom
U722  -  [TPS22965DSGR_SON8_2X2]  154.96 75.24 270 top
UA1  -  [ALC5505_QFN48_7X7]  128.11 47.77 180 top
UA2  -  [74AUP1G07GW_TSSOP5]  115.56 40.5 90 top
UA3  -  [74AUP1G07GW_TSSOP5]  115.56 37.58 90 top
UC1  -  [74AUP1G07GW_TSSOP5]  52.23 60.17 270 bottom
UCPU1  -  [SHARK-BAY-ULT_BGA_1168P-T]  96.62 79.85 0 bottom
UD1  -  [MT41J256M16RE-15E-D_FBGA_96P]  25.48 41.27 180 bottom
UD2  -  [MT41J256M16RE-15E-D_FBGA_96P]  37.04 41.27 180 bottom
UD3  -  [AT24C02C-XHM-T_TSSOP8]  44.01 49.15 90 bottom
UD4  -  [MT41J256M16RE-15E-D_FBGA_96P]  50.12 41.27 180 bottom
UD5  -  [MT41J256M16RE-15E-D_FBGA_96P]  61.68 41.27 180 bottom
UD6  -  [MT41J256M16RE-15E-D_FBGA_96P]  73.23 41.27 180 bottom
UD7  -  [MT41J256M16RE-15E-D_FBGA_96P]  84.79 41.27 180 bottom
UD8  -  [AT24C02C-XHM-T_TSSOP8]  52.39 49.14 90 bottom
UD9  -  [MT41J256M16RE-15E-D_FBGA_96P]  97.87 41.27 180 bottom
UD10  -  [MT41J256M16RE-15E-D_FBGA_96P]  109.43 41.27 180 bottom
UH5  -  [SN74AHC1G08DCKR_SC70-5]  119.71 55.84 180 bottom
US1  -  [TPS2543RTER_QFN16_3X3]  205.25 42.54 270 top
US2  -  [G547I1P81U_MSOP8]  213.27 48.37 0 top
UV1  -  [SN74CBT3257CPWR_TSSOP16]  196.69 77.03 270 top
Y1  -  [Y_CM31532768DZFT_2P]  155.02 69.81 0 top
Y2  -  [Y_7A08000006_2P]  164.98 70.19 180 top
Y3  -  [Y_Q13FC1350000200_2P]  107.28 53.21 270 top
YA1  -  [Y_X3G024000DC1H_4P]  127.35 51.06 0 top
YH1  -  [Y_CM31532768DZFT_2P]  103.8 50.16 180 bottom
YH2  -  [Y_X3G024000DC1H_4P]  85.84 85.5 180 top

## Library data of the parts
C265 C276-C283 C285 C286 C352 C355 C612 C613 C617 C621 C623 C655 C656 C713 C715 C720-C722 C963 C964 C966 C970 C974 C976-C979 C1060-C1065 C1078 C1098-C1102 C1107 C1108 C1110 C1116-C1118 C1122-C1125 C1134-C1140 C1142 C1145 C1146 C1149 C1152 C1158 C1160 C1161 C1163 C1173-C1197 C1199 C1200 C1202-C1205 C1212-C1215 C1219 C1225 C1227 C1228 C1230 C1237 C1241-C1244 C1246 C1248 C1254 C1256 C1257 C1259-C1262 C1278-C1289 C1292 C1294-C1300 CA4-CA6 CA10-CA18 CC233 CC234 CC238-CC240 CD1-CD5 CD14-CD19 CD23-CD28 CD37-CD42 CD45-CD49 CD58-CD63 CD67-CD72 CD81-CD86 CD89-CD98 CD102-CD107 CD111 CD112 CD115 CD116 CD119 CD120 CD123 CD124 CH1-CH6 CH11 CH16 CH23 CH24 CH39-CH41 CH47 CH82-CH85 CH95 CH1202 CH1203 CH1205-CH1207 CH1213-CH1216 CH1218 CH1222 CH1224 CH1226 CH1227 CH1229 CH1231-CH1236 CH1241 CV2 CV13 CV14 MC94 MC102 MC103 MC118 MC284 MC654 MC1133 MC1141 MC1151 MC1210 MC1267-MC1277 MC1297 PC101-PC109 PC112 PC113 PC116 PC202 PC203 PC206 PC208-PC212 PC216 PC220 PC227 PC229 PC304 PC308 PC312 PC316 PC320 PC324 PC328 PC332 PC336 PC340 PC404 PC408 PC412 PC415 PC501 PC502 PC509 PC511 PC512 PC603 PC604 PC609 PC614-PC616 PC703 PC704 PC708-PC711 PC714 PC716 PC718 PC719 PC721 PC724 = C_0402
C293 C712 C716 C719 C962 C965 C968 C969 C1059 C1143 C1148 C1153 C1159 C1162 C1172 C1209 C1231 C1240 CA1-CA3 CA7-CA9 CA19-CA22 CC160-CC165 CD20 CD21 CD43 CD44 CD64 CD65 CD87 CD88 CD101 CD110 CD113 CD114 CD117 CD118 CD121 CD122 CD125 CD126 CH1204 CH1217 CH1220 CH1223 CH1225 CH1239 CV1 PC114 PC115 PC213 PC218 PC221 PC228 PC307 PC315 PC323 PC331 PC339 PC407 PC416 PC503 PC504 PC605 PC608 PC612 PC613 PC707 PC712 PC713 PC715 PC717 PC720 PC722 PC723 = C_0603
C303 C1109 CH1230 = C_1206
CD22 CD66 = C_B2
CH1208-CH1211 CV15 PC204 PC205 PC214 PC217 PC219 PC223-PC225 PC302 PC303 PC305 PC306 PC310 PC311 PC313 PC314 PC318 PC319 PC321 PC322 PC326 PC327 PC329 PC330 PC334 PC335 PC337 PC338 PC341 PC342 PC403 PC405 PC410 PC411 PC413 PC414 PC505-PC508 PC510 PC513 PC602 PC606 PC607 PC701 PC702 PC801-PC830 = C_0805
CH1212 CH1228 CH1240 = C_A1
CH1237 CH1238 CV6 = C_0402: signal model: C_0402NEW_C_0402NEW
CLRP1-CLRP3 RH442 RH443 = SHORTPADS: User Part Number: PART#
CS42 CS43 CS53 CS54 CV3-CV5 CV7-CV12 = C_0402: signal model: C_0402NEW
D72 D93 D104 D105 D115 PD306 PD307 RTCD1 = BAT54CW-7-F_SOT323-3
D73 D74 D81 D84 D85 D92 D94 D114 PD305 = SDMK0340L-7-F_SOD323-2
D109 = RB751V-40GTE-17_SOD323-2
D113 = BAT1000-7-F_SOT23-3
DE1 DE2 = PESD5V0U2BT_SOT23-3
DPF1 = F_1206L150PR
F1 = F_1812L075-24DR
FD1-FD6 = FIDUCIAL_C40M80
H1 H5 H6 H8 = H_2P3
H3 = H_4P0
H9-H12 H14 = H_3P2
H13 = H_4P5N
H16 = H_2P0X2P5N
H17 = H_2P0N
H26 = H_3P3
JAPS = E-T_6705K-Y18N-00L_18P
JBATT1 = FOX_GS73091-10272-7H_9P-T
JBL1 = ACES_50519-00401-P01_4P-T
JBT1 = ACES_50271-00201-001_2P
JDCIN1 = ACES_50281-00501-001_5P-T
JDEBUG = ACES_50281-0120N-001_12P
JFAN1 = ACES_50281-0040N-001_4P
JIOL1 = E-T_1001-F36E-03R_36P
JKB1 = ACES_50699-03041-001_30P-T
JLVDS1 JLVDS2 = ACES_50406-02071-001_20P
JMDP1 = ACON_MAR2B-20K1200_20P-T
JNFC1 = HB_A531515-SCHR21_15P-T
JNGFF1 = LOTES_APCI0019-P001A01_67P-T
JSATA1 = TYCO_2041119-1_52P
JSNRDG = ACES_50506-02041-P01_20P
JTP1 = ACES_51524-00801-001_8P
JUSB1 = TAIWI_USB014-107CRL-TW_10P-T
JUSB2 = ACON_TARAG-9V1391_9P-T
JXDP = SAMTE_BSH-030-01-L-D-A_60P
L43 L44 = KC_FBMA-L11-160808-800LMT_2P
L61-L63 LH10-LH12 = MURAT_LQM2MPN2R2NG0L_2P
LA1 = CYNTE_PG031B-4R7MS_2P
LED1-LED5 = LED_27-11-T1D-CP1Q1RY-3C_2P
MD1 MD2 = RCLAMP0524PATCT_SLP2510P8-10-9
MD50 MD90 = IP4223CZ6_SO6-6
MD74 MD82 = AZ1065-06QPRDG_MSOP8
ML9 PR202 PR211 PR506 PR601 PR606 PR715 PR725 PR730 PR731 R531 R811 R1306 RH351 RH354 RH405 RH406 = R_0603
ML40 ML49 ML52 ML55 = SW_WCM2012F2S_4P
ML45 ML46 ML53 ML54 ML56-ML58 = MURAT_DLW21SN670HQ2L_4P
MR226 MR256 MR976 PH101 PH701-PH703 PR102-PR113 PR115-PR121 PR123-PR126 PR203 PR206 PR208 PR213 PR223-PR226 PR230 PR301 PR305-PR308 PR315-PR318 PR325-PR328 PR335-PR338 PR341 PR342 PR345-PR348 PR407 PR408 PR411 PR419 PR420 PR424 PR501 PR503 PR505 PR508 PR509 PR604 PR608 PR610 PR611 PR613 PR615 PR701-PR714 PR717 PR718 PR720 PR721 PR723 PR724 PR726-PR729 PR733 PR735-PR738 PR744 PR746 R219 R221 R222 R225 R229 R230 R240 R241 R250 R262 R296-R298 R300 R535-R537 R540 R545 R555 R556 R560 R565 R604 R607 R608 R854 R855 R884 R886 R888-R893 R910-R913 R916 R920 R922 R924 R927-R930 R939 R941-R945 R953 R955 R957 R973 R975 R977 R978 R980 R985 R986 R989 R990 R1003-R1005 R1026 R1027 R1032-R1034 R1088 R1090-R1092 R1099 R1100 R1103 R1115-R1118 R1132 R1136 R1137 R1139-R1143 R1154 R1156 R1160-R1165 R1167 R1169 R1175 R1176 R1179 R1180 R1182 R1183 R1185-R1187 R1190 R1191 R1197 R1198 R1200 R1202 R1203 R1206 R1207 R1209-R1215 R1217-R1220 R1223-R1225 R1227 R1228 R1239 R1241 R1249-R1251 R1253 R1255 R1261-R1266 R1279 R1281-R1287 R1289-R1292 R1295-R1297 R1299 R1307-R1313 R1324 R1325 R1338 R1341 R1342 R1346-R1351 R1354 R1360-R1371 R1375-R1381 R1384-R1389 R1391 R1394 R1395 RA1 RA5-RA8 RA16-RA20 RC36 RC41 RC43-RC46 RC48 RC52 RC54 RC55 RC58 RC60 RC75 RC81 RC93 RC95 RC97 RC100 RC138 RC146 RC149 RC153-RC156 RC158-RC161 RD1-RD90 RH2 RH11 RH12 RH21 RH23-RH25 RH29 RH31 RH32 RH34 RH35 RH37-RH40 RH42 RH43 RH51 RH53 RH54 RH56 RH70 RH72 RH76-RH79 RH91 RH95 RH98-RH100 RH103 RH105 RH107 RH110 RH111 RH113 RH117 RH123 RH126 RH146 RH147 RH151 RH154 RH158 RH159 RH163 RH168 RH171 RH180 RH183 RH186 RH188 RH196 RH248 RH255 RH270-RH272 RH274 RH281 RH282 RH294 RH295 RH300 RH302 RH303 RH310 RH314-RH316 RH337 RH338 RH360 RH363-RH365 RH367 RH369-RH375 RH380 RH381 RH383 RH384 RH386 RH390-RH392 RH394-RH398 RH400-RH402 RH410-RH416 RH423-RH426 RH428 RH429 RH431 RH434 RH435 RH438-RH441 RH444-RH446 RH451-RH454 RH457-RH463 RH465 RTCR1 RV2-RV4 RV9 RV10 = R_0402
PC610 PC611 = C_B
PC705 = C_D2
PD103 PD104 = TP0610K-T1-E3_SOT23-3
PD201 PD202 = RB751V-40_SOD323-2
PD204 = D_EC31QS04
PD301-PD303 = RB751V-40TE17_SOD323-2
PJP302 PJP304 PJP306 PJP308 PJP310 PJP701 = JUMP_43X79
PJP401-PJP404 PJP603 PJP604 = JUMP_43X39
PJP501 PJP602 = JUMP_43X118
PL101 PL104 PL201 PL202 PL501 PL601 PL703 = KC_FBMA-L11-201209-221LMA30_2P
PL102 = MURAT_BLM18BD102SN1D_L0603_2P
PL103 = L_1812-1806
PL203 PL502 PL602 = CYNTE_PCMB063T-2R2MS_2P
PL301 PL303 PL305 PL307 PL309 = CYNTE_PCME051E-2R2MS_2P
PL302 PL304 PL306 PL308 PL310 = MURAT_BLM18SG700TN1D_2P
PL401 PL402 = CYNTE_PHI25201B-2R2MS_2P
PL701 PL702 = TOKO_FDUM0640J-H-R36M-P3_4P
PQ101 = FDV301N_NL_SOT23-3
PQ102 = RHU002N06_SOT323-3
PQ103 PQ105 = 2N7002KDWH_SOT363-6
PQ104 PQ106 PQ202 PQ204 PQ300 Q4 Q5 Q34 Q39 Q71 Q305 Q311 Q326 Q344 Q346 Q351 Q362-Q364 QC5 = SSM3K7002FU_SC70-3
PQ201 = CSD87312Q3E_SON8-4
PQ203 = SIR472DP-T1-GE3_POWERPAK8-5
PQ205 = SI7716ADN-T1-GE3_POWERPAK8-5
PQ206 = AO4407AL_SO8
PQ601 = AON7406L_DFN8-5
PQ602 = AON7212L_DFN8-5
PR122 PR209 PR210 PR220 PR304 PR314 PR324 PR334 PR344 PR406 PR418 PR507 PR605 PR719 PR734 R1240 R1355 RV1 = R_1206
PR201 PR216 = R_1206_4P-D
PU201 = BQ24715RGRR_QFN20_3P5X3P5
PU301-PU305 = TPS62130RGTR_QFN16_3X3
PU306 = G920AT24U_SOT89-3
PU307 U689 U699 = SN74AHC1G32DCKR_SC70-5
PU401 = TPS62150RGTR_QFN16_3X3
PU402 = TPS62140RGTR_QFN16_3X3
PU501 = TPS51362RVER_QFN28_4P5X3P5
PU601 = RT8207MZQW_WQFN20_3X3
PU701 = TPS51622RSM_QFN32_4X4
PU702 PU703 = CSD97374CQ4M_SON8_3P5X4P5-S
Q70 = SI3457BDV-T1-E3_TSOP6
Q316 Q318 Q320 Q349 Q352 Q359 QH3 QH4 = DMN66D0LDW-7_SOT363-6
Q329 Q354-Q358 = AO3419L_SOT23-3
Q347 = MMBT3904_SOT23-3
Q360 = SIS412DN-T1-GE3_POWERPAK8-5
Q361 = SI1553CDL-T1-GE3_SC70-6
QV2 = BSS138-G_SOT23-3
R216 R1125 R1128 R1226 R1242 R1305 R1318-R1320 R1326 R1392 R1393 RH350 = R0603_0OHM
R228 R249 R253 R265 R741 R742 R819 R921 R925 R926 R931 R934 R974 R982-R984 R1006-R1011 R1131 R1133 R1135 R1146 R1152 R1153 R1158 R1166 R1188 R1199 R1204 R1205 R1208 R1216 R1221 R1222 R1238 R1247 R1252 R1257 R1258 R1293 R1294 R1314 R1353 R1382 R1390 RA9-RA15 RC49 RC98 RC99 RC147 RC148 RC150-RC152 RC162 RH128 RH131-RH133 RH137 RH293 RH297 RH309 RH313 RH341 RH346 RH348 RH355 RH356 RH427 RH430 RH450 RV8 = R0402_0OHM
R541 = R_0805
R1322 RH340 = R0805_0OHM
R1327 R1328 R1373 R1374 RC94 = R_0402: signal model: R_0402NEW_R_0402NEW
R1372 RC92 RC96 = R0402_0OHM: signal model: R_0402NEW_R_0402NEW
RP2-RP4 RP7 RP11 RP12 RP14-RP16 RP19-RP22 = RP_0804_8P4R
SW1 = SW_EVQP3S01K_4P
SW2 = SW_SKQGCBE010_4P
T2 T123 T226-T231 T242-T246 T252 T260-T293 = TPC12
U34 = KB9012BF-A3_LFBGA_128P
U48 = W25Q64FVSSIQ_SO8
U635 = SN74LVC1G06DCKR_SC70-5
U636 = STM32F103RDY6TR_WLCSP_64P
U637 = LSM303DLHCTR_LGA14_3X5
U638 = L3GD20TR_LGA16_4X4
U652 = AT97SC3204-X2A18-AB_TSSOP28
U653 = LPS331APTR_HCLGA16_3X3
U663 = 74CBTLV3126DS_SSOP16
U664 U716-U719 = TPS22966DPUR_SON14_2X3
U671 U677 = TXB0104PWR_TSSOP14
U672 UA2 UA3 UC1 = 74AUP1G07GW_TSSOP5
U673 = NCP4545IMNTWG_QFN18_3X3
U675 U690 U691 U697 U698 UH5 = SN74AHC1G08DCKR_SC70-5
U676 = SN74CBT1G125DCKR_SC70-5
U679 = TXS0102YZPR_DSBGA_8P
U682 U687 U708-U710 U712 U713 = SN74AHC1G04DCKR_SOT23-5
U688 = NC7SZ175P6X_SC70-6
U714 = 1337GNLGI8_QFN16_3X3
U721 = APL3512ABI-TRG_SOT23-5
U722 = TPS22965DSGR_SON8_2X2
UA1 = ALC5505_QFN48_7X7
UCPU1 = SHARK-BAY-ULT_BGA_1168P-T
UD1 UD2 UD4-UD7 UD9 UD10 = MT41J256M16RE-15E-D_FBGA_96P
UD3 UD8 = AT24C02C-XHM-T_TSSOP8
US1 = TPS2543RTER_QFN16_3X3
US2 = G547I1P81U_MSOP8
UV1 = SN74CBT3257CPWR_TSSOP16
Y1 YH1 = Y_CM31532768DZFT_2P
Y2 = Y_7A08000006_2P
Y3 = Y_Q13FC1350000200_2P
YA1 YH2 = Y_X3G024000DC1H_4P

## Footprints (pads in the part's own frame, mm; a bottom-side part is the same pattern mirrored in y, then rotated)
2N7002KDWH_SOT363-6
  oval 0.356x0.889 smd: 1(0,0) 2(0.65,0) 3(1.3,0) 4(1.3,1.6) 5(0.65,1.6) 6(0,1.6)
74AUP1G07GW_TSSOP5
  oval 0.381x1.346 smd: 1(0,0) 2(0.65,0) 3(1.3,0) 4(1.3,1.79) 5(0,1.79)
74CBTLV3126DS_SSOP16
  oval 0.381x1.676 smd: 1(0,0) 2(0.635,0) 3(1.27,0) 4(1.905,0) 5(2.54,0) 6(3.175,0) 7(3.81,0) 8(4.445,0) 9(4.445,5.35) 10(3.81,5.35) 11(3.175,5.35) 12(2.54,5.35) 13(1.905,5.35) 14(1.27,5.35) 15(0.635,5.35) 16(0,5.35)
1337GNLGI8_QFN16_3X3
  oval 0.254x1.016 smd: 1(0,0) 2(0.5,0) 3(1,0) 4(1.5,0) 9(1.5,2.975) 10(1,2.975) 11(0.5,2.975) 12(0,2.975)
  oval 1.016x0.254 smd: 5(2.238,0.738) 6(2.238,1.238) 7(2.238,1.738) 8(2.238,2.238) 13(-0.738,2.238) 14(-0.738,1.738) 15(-0.738,1.238) 16(-0.738,0.738)
  rect 1.676x1.676 smd: 17(0.75,1.488)
ACES_50271-00201-001_2P
  oval 0.787x1.6 smd: 1(0,0) 2(1.25,0)
  rect 2.108x2.997 smd: 3(-2.55,-2.9) 4(3.8,-2.9)
ACES_50281-0040N-001_4P
  oval 0.787x2.007 smd: 1(0,0) 2(-1.25,0) 3(-2.5,0) 4(-3.75,0)
  rect 2.007x2.489 smd: 5(2.2,-4.05) 6(-5.95,-4.05)
ACES_50281-0120N-001_12P
  oval 0.787x2.007 smd: 1(0,0) 2(-1.25,0) 3(-2.5,0) 4(-3.75,0) 5(-5,0) 6(-6.25,0) 7(-7.5,0) 8(-8.75,0) 9(-10,0) 10(-11.25,0) 11(-12.5,0) 12(-13.75,0)
  rect 2.007x2.489 smd: 13(2.2,-4.05) 14(-15.95,-4.05)
ACES_50281-00501-001_5P-T
  oval 0.787x2.007 smd: 1(0,0) 2(1.25,0) 3(2.5,0) 4(3.75,0) 5(5,0)
  rect 2.007x2.489 smd: 6(7.2,-4.05) 7(-2.2,-4.05)
ACES_50406-02071-001_20P
  oval 0.254x1.295 smd: 1(0,0) 2(0.5,0) 3(1,0) 4(1.5,0) 5(2,0) 6(2.5,0) 7(3,0) 8(3.5,0) 9(4,0) 10(4.5,0) 11(5,0) 12(5.5,0) 13(6,0) 14(6.5,0) 15(7,0) 16(7.5,0) 17(8,0) 18(8.5,0) 19(9,0) 20(9.5,0)
  rect 1.194x2.692 smd: 21(-2.4,1.95) 22(11.9,1.95)
  rect 2.311x1.295 smd: 23(0.85,3.9) 24(8.65,3.9)
ACES_50506-02041-P01_20P
  oval 0.305x0.889 smd: 1(0,0) 2(0.5,0) 3(1,0) 4(1.5,0) 5(2,0) 6(2.5,0) 7(3,0) 8(3.5,0) 9(4,0) 10(4.5,0) 11(5,0) 12(5.5,0) 13(6,0) 14(6.5,0) 15(7,0) 16(7.5,0) 17(8,0) 18(8.5,0) 19(9,0) 20(9.5,0)
  rect 0.991x2.007 smd: 21(-2.1,-3.05) 22(11.6,-3.05)
ACES_50519-00401-P01_4P-T
  oval 0.508x1.448 smd: 1(0,0) 2(0.8,0) 3(1.6,0) 4(2.4,0)
  rect 1.803x1.905 smd: 5(-2.3,-3.125) 6(4.7,-3.125)
ACES_50699-03041-001_30P-T
  oval 0.229x0.787 smd: 1(0,0) 2(0.8,0) 3(1.6,0) 4(2.4,0) 5(3.2,0) 6(4,0) 7(4.8,0) 8(5.6,0) 9(6.4,0) 10(7.2,0) 11(8,0) 12(8.8,0) 13(9.6,0) 14(10.4,0) 15(11.2,0) 16(12,0) 17(12.8,0) 18(13.6,0) 19(14.4,0) 20(15.2,0) 21(16,0) 22(16.8,0) 23(17.6,0) 24(18.4,0) 25(19.2,0) 26(20,0) 27(20.8,0) 28(21.6,0) 29(22.4,0) 30(23.2,0)
  rect 0.559x1.295 smd: 31(-1.475,-3.3) 32(24.675,-3.3)
ACES_51524-00801-001_8P
  oval 0.61x1.295 smd: 1(0,0) 2(1,0) 3(2,0) 4(3,0) 5(4,0) 6(5,0) 7(6,0) 8(7,0)
  rect 2.489x2.21 smd: 9(-3,-3.05) 10(10,-3.05)
ACON_MAR2B-20K1200_20P-T
  round 0.94 hole 0.94 unplated: (-0.825,3.26) (6.825,3.26)
  oval 0.813x0.914 hole 0.61: 1(0,0) 3(0.5,1) 5(1.5,1) 7(2,0) 9(2.5,-1) 11(3.5,-1) 13(4,0) 15(4.5,1) 17(5.5,1) 19(6,0)
  oval 0.356x2.007 smd: 2(0.3,2.91) 4(0.9,2.91) 6(1.5,2.91) 8(2.1,2.91) 10(2.7,2.91) 12(3.3,2.91) 14(3.9,2.91) 16(4.5,2.91) 18(5.1,2.91) 20(5.7,2.91)
  oval 1.092x2.007 hole 0.711x1.6: 21(-2.1,1.66) 23(8.1,1.66)
  oval 1.092x1.803 hole 0.711x1.397: 22(-2.8,-3.04) 24(8.8,-3.04)
ACON_TARAG-9V1391_9P-T
  round 1.295 hole 0.711: 1(0,0) 2(-2.5,0) 3(-4.5,0) 4(-7,0) 5(-7.5,-1.5) 6(-5.5,-1.5) 7(-3.5,-1.5) 8(-1.5,-1.5) 9(0.5,-1.5)
  oval 1.499x2.489 hole 0.889x1.905: 10(-9.9,-0.75) 13(2.9,-0.75)
  oval 1.499x2.21 hole 0.889x1.6: 11(-11.35,-9.2) 12(4.35,-9.2)
ALC5505_QFN48_7X7
  oval 0.254x1.041 smd: 1(0,0) 2(0.5,0) 3(1,0) 4(1.5,0) 5(2,0) 6(2.5,0) 7(3,0) 8(3.5,0) 9(4,0) 10(4.5,0) 11(5,0) 12(5.5,0) 25(5.5,6.95) 26(5,6.95) 27(4.5,6.95) 28(4,6.95) 29(3.5,6.95) 30(3,6.95) 31(2.5,6.95) 32(2,6.95) 33(1.5,6.95) 34(1,6.95) 35(0.5,6.95) 36(0,6.95)
  oval 1.041x0.254 smd: 13(6.225,0.725) 14(6.225,1.225) 15(6.225,1.725) 16(6.225,2.225) 17(6.225,2.725) 18(6.225,3.225) 19(6.225,3.725) 20(6.225,4.225) 21(6.225,4.725) 22(6.225,5.225) 23(6.225,5.725) 24(6.225,6.225) 37(-0.725,6.225) 38(-0.725,5.725) 39(-0.725,5.225) 40(-0.725,4.725) 41(-0.725,4.225) 42(-0.725,3.725) 43(-0.725,3.225) 44(-0.725,2.725) 45(-0.725,2.225) 46(-0.725,1.725) 47(-0.725,1.225) 48(-0.725,0.725)
  rect 5.461x5.461 smd: 49(2.75,3.475)
AO3419L_SOT23-3
  oval 1.016x1.524 smd: 1(0,0) 2(0.965,2.083) 3(-0.965,2.083)
AO4407AL_SO8
  oval 0.635x1.854 smd: 1(0,0) 2(1.27,0) 3(2.54,0) 4(3.81,0) 5(3.81,5.165) 6(2.54,5.165) 7(1.27,5.165) 8(0,5.165)
AON7212L_DFN8-5
  oval 0.406x0.991 smd: 1(0,0) 2(0.66,0) 3(1.32,0) 4(1.98,0)
  custom 0.559x0.559 smd: 5(0.99,2.247)
AON7406L_DFN8-5
  oval 0.406x0.991 smd: 1(0,0) 2(0.66,0) 3(1.32,0) 4(1.98,0)
  custom 0.559x0.559 smd: 5(0.99,2.247)
APL3512ABI-TRG_SOT23-5
  oval 0.61x1.041 smd: 1(0,0) 2(0.95,0) 3(1.9,0) 4(1.9,2.7) 5(0,2.7)
AT24C02C-XHM-T_TSSOP8
  oval 0.381x1.626 smd: 1(0,0) 2(0.65,0) 3(1.3,0) 4(1.95,0) 5(1.95,5.8) 6(1.3,5.8) 7(0.65,5.8) 8(0,5.8)
AT97SC3204-X2A18-AB_TSSOP28
  oval 0.381x1.626 smd: 1(0,0) 2(0.65,0) 3(1.3,0) 4(1.95,0) 5(2.6,0) 6(3.25,0) 7(3.9,0) 8(4.55,0) 9(5.2,0) 10(5.85,0) 11(6.5,0) 12(7.15,0) 13(7.8,0) 14(8.45,0) 15(8.45,5.8) 16(7.8,5.8) 17(7.15,5.8) 18(6.5,5.8) 19(5.85,5.8) 20(5.2,5.8) 21(4.55,5.8) 22(3.9,5.8) 23(3.25,5.8) 24(2.6,5.8) 25(1.95,5.8) 26(1.3,5.8) 27(0.65,5.8) 28(0,5.8)
AZ1065-06QPRDG_MSOP8
  oval 0.381x1.575 smd: 1(0,0) 2(0.65,0) 3(1.3,0) 4(1.95,0) 5(1.95,4.35) 6(1.3,4.35) 7(0.65,4.35) 8(0,4.35)
BAT54CW-7-F_SOT323-3
  oval 0.711x0.889 smd: 1(0,0) 2(-0.65,-1.9) 3(0.65,-1.9)
BAT1000-7-F_SOT23-3
  oval 1.016x1.524 smd: 1(0,0) 2(0.965,2.083) 3(-0.965,2.083)
BQ24715RGRR_QFN20_3P5X3P5
  oval 0.254x1.041 smd: 1(0,0) 2(0.5,0) 3(1,0) 4(1.5,0) 5(2,0) 11(2,3.45) 12(1.5,3.45) 13(1,3.45) 14(0.5,3.45) 15(0,3.45)
  oval 1.041x0.254 smd: 6(2.725,0.725) 7(2.725,1.225) 8(2.725,1.725) 9(2.725,2.225) 10(2.725,2.725) 16(-0.725,2.725) 17(-0.725,2.225) 18(-0.725,1.725) 19(-0.725,1.225) 20(-0.725,0.725)
  rect 2.057x2.057 smd: 21(1,1.725)
BSS138-G_SOT23-3
  oval 1.016x1.524 smd: 1(0,0) 2(0.965,2.083) 3(-0.965,2.083)
C_0402
  rect 0.508x0.559 smd: 1(0,0) 2(0.914,0)
C_0603
  rect 0.635x0.889 smd: 1(0,0) 2(1.397,0)
C_0805
  rect 0.813x1.397 smd: 1(0,0) 2(1.702,0)
C_1206
  rect 1.016x1.651 smd: 1(0,0) 2(2.667,0)
C_A1
  rect 1.346x1.499 smd: 1(0,0) 2(2.45,0)
C_B
  rect 1.549x2.464 smd: 1(0,0) 2(3.378,0)
C_B2
  rect 1.346x2.692 smd: 1(0,0) 2(-2.75,0)
C_D2
  rect 2.388x2.794 smd: 1(0,0) 2(6.4,0)
CSD87312Q3E_SON8-4
  rect 2.388x0.66 smd: 1(0,0)
  rect 0.432x0.66 smd: 2(0.975,2.95)
  rect 1.753x0.66 smd: 3(-0.325,2.95)
  custom 0.475x0.475 smd: 4(0,1.475)
CSD97374CQ4M_SON8_3P5X4P5-S
  oval 0.203x0.914 smd: 1(0,0) 2(0.4,0) 3(0.8,0) 6(0.8,3.505) 7(0.4,3.505) 8(0,3.505)
  custom 0.225x0.225 smd: 4(2.2,0.265) 5(2.2,3.24)
  rect 4.039x2.21 smd: 9(1.6,1.752)
CYNTE_PCMB063T-2R2MS_2P
  rect 2.159x3.505 smd: 1(0,0) 2(5.85,0)
CYNTE_PCME051E-2R2MS_2P
  rect 1.905x2.489 smd: 1(0,0) 2(4.095,0)
CYNTE_PG031B-4R7MS_2P
  rect 0.889x1.194 smd: 1(0,0) 2(2.2,0)
CYNTE_PHI25201B-2R2MS_2P
  rect 0.889x2.108 smd: 1(0,0) 2(1.7,0)
D_EC31QS04
  rect 2.235x2.032 smd: 1(1.9,0) 2(-1.9,0)
DMN66D0LDW-7_SOT363-6
  oval 0.432x0.61 smd: 1(0,0) 2(0.65,0) 3(1.3,0) 4(1.3,1.9) 5(0.65,1.9) 6(0,1.9)
E-T_1001-F36E-03R_36P
  round 0.711 hole 0.711 unplated: (-1.25,-2.425) (9.75,-2.425)
  oval 0.381x1.143 smd: 1(0,0) 2(0,-4.85) 35(8.5,0) 36(8.5,-4.85)
  oval 0.254x1.143 smd: 3(0.5,0) 4(0.5,-4.85) 5(1,0) 6(1,-4.85) 7(1.5,0) 8(1.5,-4.85) 9(2,0) 10(2,-4.85) 11(2.5,0) 12(2.5,-4.85) 13(3,0) 14(3,-4.85) 15(3.5,0) 16(3.5,-4.85) 17(4,0) 18(4,-4.85) 19(4.5,0) 20(4.5,-4.85) 21(5,0) 22(5,-4.85) 23(5.5,0) 24(5.5,-4.85) 25(6,0) 26(6,-4.85) 27(6.5,0) 28(6.5,-4.85) 29(7,0) 30(7,-4.85) 31(7.5,0) 32(7.5,-4.85) 33(8,0) 34(8,-4.85)
  custom 0.4x0.4 smd: 37(10.7,-2.425) 38(-2.2,-2.425)
E-T_6705K-Y18N-00L_18P
  oval 0.305x1.092 smd: 1(0,0) 2(-0.5,0) 3(-1,0) 4(-1.5,0) 5(-2,0) 6(-2.5,0) 7(-3,0) 8(-3.5,0) 9(-4,0) 10(-4.5,0) 11(-5,0) 12(-5.5,0) 13(-6,0) 14(-6.5,0) 15(-7,0) 16(-7.5,0) 17(-8,0) 18(-8.5,0)
  rect 0.991x2.007 smd: 19(2.1,-3.15) 20(-10.6,-3.15)
F_1206L150PR
  rect 0.991x1.803 smd: 1(0,0) 2(2.8,0)
F_1812L075-24DR
  rect 1.778x3.15 smd: 1(0,0) 2(5.23,0)
FDV301N_NL_SOT23-3
  oval 1.016x1.524 smd: 1(0,0) 2(0.965,2.083) 3(-0.965,2.083)
FIDUCIAL_C40M80
  round 1.016 smd: 1(0,0)
FOX_GS73091-10272-7H_9P-T
  rect 0.66x5.004 smd: 1(0,0) 2(-1.5,0) 3(-3,0) 4(-4.5,0) 5(-6,0) 6(-7.5,0) 7(-9,0) 8(-10.5,0) 9(-12,0)
  rect 2.489x2.997 smd: 10(-14.5,4.45) 11(2.5,4.45)
G547I1P81U_MSOP8
  oval 0.381x1.549 smd: 1(0,0) 2(0.65,0) 3(1.3,0) 4(1.95,0) 5(1.95,4.37) 6(1.3,4.37) 7(0.65,4.37) 8(0,4.37)
G920AT24U_SOT89-3
  rect 1.118x1.524 smd: 1(0,0) 3(2.997,0)
  custom 0.508x0.508 smd: 2(1.499,1.778)
H_2P0N
  round 2.007 hole 2.007 unplated: (0,0)
H_2P0X2P5N
  oval 2.007x2.489 hole 2.007x2.489 unplated: (0,0)
H_2P3
  round 2.819 hole 2.311: 1(0,0)
H_3P2
  round 3.708 hole 3.2: 1(0,0)
H_3P3
  round 3.81 hole 3.302: 1(0,0)
H_4P0
  round 4.496 hole 3.988: 1(0,0)
H_4P5N
  round 4.496 hole 4.496 unplated: (0,0)
HB_A531515-SCHR21_15P-T
  oval 0.305x0.889 smd: 1(0,0) 2(0.5,0) 3(1,0) 4(1.5,0) 5(2,0) 6(2.5,0) 7(3,0) 8(3.5,0) 9(4,0) 10(4.5,0) 11(5,0) 12(5.5,0) 13(6,0) 14(6.5,0) 15(7,0)
  rect 0.991x2.007 smd: 16(-2.1,-3.05) 17(9.1,-3.05)
IP4223CZ6_SO6-6
  oval 0.508x1.422 smd: 1(0,0) 2(0.95,0) 3(1.9,0) 4(1.9,2.35) 5(0.95,2.35) 6(0,2.35)
JUMP_43X39
  custom 0.191x0.191 smd: 1(0,0) 2(0.914,0)
JUMP_43X79
  custom 0.188x0.188 smd: 1(0,0) 2(1.1,0)
JUMP_43X118
  custom 0.187x0.187 smd: 1(0,0) 2(1.1,0)
KB9012BF-A3_LFBGA_128P
  round 0.254 smd: A1(0,0) A2(0.5,0) A3(1,0) A4(1.5,0) A5(2,0) A6(2.5,0) A7(3,0) A8(3.5,0) A9(4,0) A10(4.5,0) A11(5,0) A12(5.5,0) A13(6,0) B1(0,-0.5) B2(0.5,-0.5) B3(1,-0.5) B4(1.5,-0.5) B5(2,-0.5) B6(2.5,-0.5) B7(3,-0.5) B8(3.5,-0.5) B9(4,-0.5) B10(4.5,-0.5) B11(5,-0.5) B12(5.5,-0.5) B13(6,-0.5) C1(0,-1) C2(0.5,-1) C12(5.5,-1) C13(6,-1) D1(0,-1.5) D2(0.5,-1.5) D4(1.5,-1.5) D5(2,-1.5) D6(2.5,-1.5) D7(3,-1.5) D8(3.5,-1.5) D9(4,-1.5) D10(4.5,-1.5) D12(5.5,-1.5) D13(6,-1.5) E1(0,-2) E2(0.5,-2) E4(1.5,-2) E5(2,-2) E6(2.5,-2) E7(3,-2) E8(3.5,-2) E9(4,-2) E10(4.5,-2) E12(5.5,-2) E13(6,-2) F1(0,-2.5) F2(0.5,-2.5) F4(1.5,-2.5) F5(2,-2.5) F9(4,-2.5) F10(4.5,-2.5) F12(5.5,-2.5) F13(6,-2.5) G1(0,-3) G2(0.5,-3) G4(1.5,-3) G5(2,-3) G9(4,-3) G10(4.5,-3) G12(5.5,-3) G13(6,-3) H1(0,-3.5) H2(0.5,-3.5) H4(1.5,-3.5) H5(2,-3.5) H9(4,-3.5) H10(4.5,-3.5) H12(5.5,-3.5) H13(6,-3.5) J1(0,-4) J2(0.5,-4) J4(1.5,-4) J5(2,-4) J6(2.5,-4) J7(3,-4) J8(3.5,-4) J9(4,-4) J10(4.5,-4) J12(5.5,-4) J13(6,-4) K1(0,-4.5) K2(0.5,-4.5) K4(1.5,-4.5) K5(2,-4.5) K6(2.5,-4.5) K7(3,-4.5) K8(3.5,-4.5) K9(4,-4.5) K10(4.5,-4.5) K12(5.5,-4.5) K13(6,-4.5) L1(0,-5) L2(0.5,-5) L12(5.5,-5) L13(6,-5) M1(0,-5.5) M2(0.5,-5.5) M3(1,-5.5) M4(1.5,-5.5) M5(2,-5.5) M6(2.5,-5.5) M7(3,-5.5) M8(3.5,-5.5) M9(4,-5.5) M10(4.5,-5.5) M11(5,-5.5) M12(5.5,-5.5) M13(6,-5.5) N1(0,-6) N2(0.5,-6) N3(1,-6) N4(1.5,-6) N5(2,-6) N6(2.5,-6) N7(3,-6) N8(3.5,-6) N9(4,-6) N10(4.5,-6) N11(5,-6) N12(5.5,-6) N13(6,-6)
